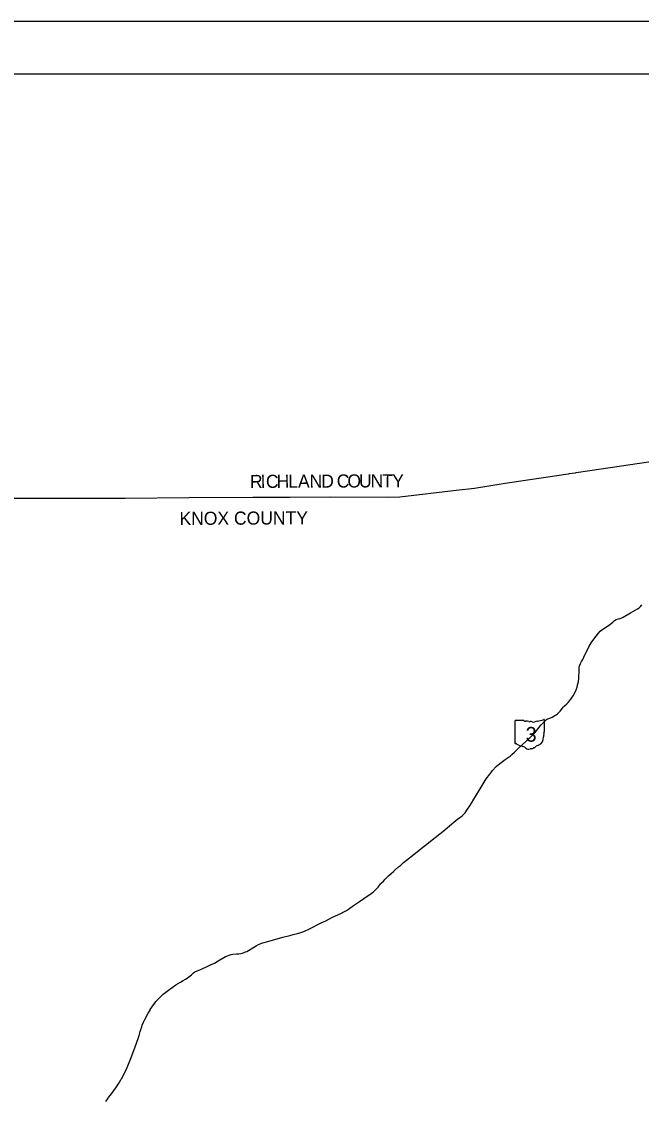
# Model space of a CAD drawing. Extents: x 1851937 to 2123937, y 78841 to 965467.
# Drawn here: x 1974387 to 2021685, y 883220 to 965467 of the extents above; entities that cross this region are included whole.
import ezdxf

# ---------------------------------------------------------------- set-up
doc = ezdxf.new("R2010")
doc.units = 0
for name, color, linetype in [('GM_X_County', 7, 'Continuous'), ('GM_X_County_Text', 7, 'Continuous'), ('GM_X_State_Location', 7, 'Continuous'), ('GM_X_State_Route', 7, 'Continuous'), ('GM_X_State_Shield', 7, 'Continuous'), ('SH_Border', 7, 'Continuous'), ('SH_Cut_Line', 7, 'Continuous')]:
    doc.layers.add(name, color=color, linetype=linetype)

msp = doc.modelspace()

# ---------------------------------------------------------------- linework, layer by layer
at = {"layer": 'GM_X_County'}
msp.add_lwpolyline([(1973238, 929092), (1976550, 929094), (1977275, 929101), (1981905, 929098), (1982300, 929096), (1987139, 929156), (1992035, 929178), (1994867, 929187), (1997941, 929196), (2002293, 929188), (2003257, 929191), (2007557, 929722), (2008942, 929868), (2011280, 930252), (2013856, 930622), (2016096, 930955), (2016123, 930959), (2016203, 930970), (2016399, 931000), (2016621, 931036), (2016657, 931042), (2016696, 931049), (2017735, 931206), (2023098, 932000)], dxfattribs=at)
at = {"layer": 'GM_X_State_Route'}
for points in [[(2010108, 908032), (2010136, 908070), (2010329, 908319), (2010595, 908614), (2010892, 908853), (2011084, 908999), (2011295, 909161), (2011657, 909425), (2011795, 909536), (2012004, 909720), (2012284, 909987), (2013183, 910840), (2013448, 911088), (2013553, 911194), (2014002, 911771), (2014129, 911917), (2014259, 912042), (2014316, 912103), (2014386, 912159), (2014448, 912201), (2014501, 912230), (2014551, 912253), (2014688, 912315), (2014869, 912398), (2015084, 912513), (2015120, 912535), (2015190, 912578), (2015290, 912655), (2015365, 912719), (2015493, 912858), (2015587, 912968), (2015715, 913141), (2015762, 913199), (2015801, 913238), (2015989, 913404), (2016088, 913496), (2016223, 913669), (2016469, 914024), (2016613, 914237), (2016709, 914469), (2016769, 914683), (2016815, 914847), (2016852, 915007), (2016877, 915093), (2016885, 915170), (2016902, 915286), (2016909, 915436), (2016933, 915903), (2016933, 915996), (2016945, 916226), (2016958, 916290), (2016980, 916364), (2017040, 916487), (2017120, 916627), (2017218, 916798), (2017374, 917152), (2017578, 917530), (2017732, 917855), (2017904, 918129), (2018219, 918571), (2018400, 918811), (2018533, 918952), (2018752, 919116), (2019239, 919446), (2019399, 919553), (2019504, 919642), (2019573, 919716), (2019641, 919771), (2019766, 919831), (2019936, 919884), (2020071, 919925), (2020200, 919973), (2020279, 920010), (2020851, 920350), (2021028, 920454), (2021375, 920644), (2021509, 920738), (2021619, 920841), (2021725, 920964)], [(2008909, 906141), (2009099, 906460), (2009452, 907042), (2009842, 907673), (2010108, 908032)], [(2007727, 904669), (2008001, 904873), (2008120, 904968), (2008227, 905095), (2008417, 905365), (2008596, 905614), (2008730, 905839), (2008909, 906141)], [(2005587, 902928), (2006290, 903477), (2006536, 903665), (2007363, 904378), (2007672, 904628), (2007727, 904669)], [(2003481, 901248), (2003530, 901291), (2004571, 902117), (2004885, 902364)], [(2004885, 902364), (2005436, 902810), (2005587, 902928)], [(2001833, 899722), (2001992, 899870), (2002004, 899882), (2002141, 900032), (2002242, 900124), (2002397, 900283), (2002597, 900461), (2002756, 900614), (2002889, 900741), (2003155, 900970), (2003289, 901072), (2003436, 901210), (2003481, 901248)], [(2001100, 898958), (2001211, 899041), (2001303, 899117), (2001369, 899180), (2001449, 899268), (2001588, 899429), (2001778, 899670), (2001833, 899722)], [(1997591, 896860), (1998108, 897126), (1998748, 897414), (1998989, 897529), (1999173, 897631), (1999343, 897748), (1999713, 898006), (2000185, 898330), (2000506, 898554), (2001068, 898935), (2001100, 898958)], [(1985070, 891125), (1985197, 891242), (1985292, 891324), (1985603, 891553), (1986152, 891953), (1986507, 892172), (1986730, 892288), (1986904, 892396), (1987019, 892476), (1987149, 892579), (1987345, 892730), (1987516, 892872), (1987617, 892946), (1987783, 893029), (1987978, 893115), (1988215, 893221), (1988495, 893344), (1988808, 893485), (1989096, 893626), (1989400, 893806), (1989956, 894115), (1990095, 894187), (1990222, 894240), (1990374, 894277), (1990504, 894300), (1990786, 894323), (1990955, 894331), (1991108, 894349), (1991219, 894375), (1991372, 894427), (1991478, 894474), (1991571, 894514), (1992151, 894857), (1992287, 894940), (1992454, 895038), (1992594, 895105), (1992689, 895145), (1992798, 895179), (1993177, 895282), (1994325, 895603), (1994868, 895732), (1995109, 895799), (1995431, 895890), (1995686, 895956), (1995780, 895986), (1995918, 896036), (1996351, 896238), (1997253, 896694), (1997591, 896860)], [(1984188, 890039), (1984208, 890075), (1984324, 890269), (1984386, 890349), (1984546, 890566), (1984641, 890686), (1984726, 890790), (1984838, 890905), (1984910, 890981), (1985070, 891125)], [(1981033, 883370), (1981250, 883656), (1981572, 884101), (1981789, 884419), (1981995, 884755), (1982009, 884782), (1982163, 885071), (1982443, 885656), (1982796, 886554), (1983044, 887232), (1983277, 887878), (1983358, 888104), (1983440, 888403), (1983564, 888762), (1983595, 888877), (1983687, 889125), (1983733, 889226), (1983782, 889319), (1984056, 889807), (1984188, 890039)], [(1980817, 883070), (1980998, 883324), (1981033, 883370)]]:
    msp.add_lwpolyline(points, dxfattribs=at)
at = {"layer": 'GM_X_State_Shield'}
for p, q in [((2012715, 912130), (2012059, 912130)), ((2014278, 911282), (2014278, 912172)), ((2012037, 912100), (2012037, 910399)), ((2014278, 911282), (2014278, 911282))]:
    msp.add_line(p, q, dxfattribs=at)
for centre, radius, start, end in [((2012063, 912104), 26, 98.1301, 188.1301), ((2012872, 912327), 252, 231.61951, 271.11188), ((2013480, 914449), 2377, 275.84447, 288.90645), ((2014253, 912176), 25, 351.86209, 97.738), ((2012955, 911175), 904, 80.48669, 94.98827), ((2013160, 912113), 72.7, 219.79206, 297.10237), ((2013267, 911916), 151, 54.46668, 119.14113), ((2013462, 912186), 182, 233.85621, 294.82819), ((2013783, 911610), 478, 97.34618, 120.76885), ((2013613, 910796), 595, 292.30889, 8.98584), ((2014368, 910910), 169, 136.8065, 186.92959), ((2014272, 911217), 38.6, 107.94398, 210.33697), ((2014027, 911104), 232, 340.03296, 23.64957), ((2014252, 911279), 26.7, 289.60381, 7.73413), ((2012063, 910396), 26.2, 171.95839, 258.30661), ((2012067, 910570), 200, 267.33899, 280.60386), ((2012108, 910301), 72.1, 29.74838, 93.27175), ((2013018, 911830), 1716, 240.41292, 257.1985), ((2012506, 909635), 537, 47.18416, 75.83597), ((2013087, 910293), 341, 230.70037, 286.29184), ((2013284, 909705), 280, 85.69512, 111.20995), ((2013309, 910165), 182, 268.77702, 315.54927), ((2013473, 910001), 51.1, 65.75173, 132.64842), ((2013451, 910234), 192, 282.87319, 323.27711), ((2013864, 909922), 326, 94.40312, 142.57675)]:
    msp.add_arc(centre, radius, start, end, dxfattribs=at)
at = {"layer": 'SH_Border'}
msp.add_lwpolyline([(1863937, 961467), (2119937, 961467), (2119937, 793467), (1863937, 793467)], close=True, dxfattribs=at)
at = {"layer": 'SH_Cut_Line'}
msp.add_lwpolyline([(1851937, 789467), (2123937, 789467), (2123937, 965467), (1851937, 965467)], close=True, dxfattribs=at)

# ---------------------------------------------------------------- texts
at = {"layer": 'GM_X_County_Text'}
for s, rotation, p in [('R', 0.26523, (1991812, 929878)), ('I', 0.26556, (1992626, 929881)), ('C', 0.26523, (1993035, 929883)), ('H', 0.26533, (1993849, 929887)), ('L', 0.26549, (1994733, 929891)), ('A', 0.26533, (1995481, 929895)), ('N', 0.26533, (1996366, 929899)), ('D', 0.26533, (1997250, 929903)), ('C', 0.26523, (1998438, 929908)), ('O', 0.26533, (1999252, 929912)), ('U', 0.26098, (2000136, 929916)), ('N', 0.11527, (2001020, 929920)), ('T', 359.13986, (2001900, 929922)), ('Y', 1.28553, (2002689, 929911)), ('KNOX COUNTY', 0.25392, (1986435, 927055))]:
    msp.add_text(s, height=1000, rotation=rotation, dxfattribs=at).set_placement(p)
at = {"layer": 'GM_X_State_Location'}
msp.add_text('3', height=1, rotation=0.00001, dxfattribs=at).set_placement((2013001, 910620))
for s in ['s', 'r']:
    msp.add_text(s, height=1, dxfattribs=at).set_placement((2013151, 910693))
at = {"layer": 'GM_X_State_Shield'}
msp.add_text('3', height=1121, dxfattribs=at).set_placement((2012851, 910519))

doc.saveas('drawing.dxf')
